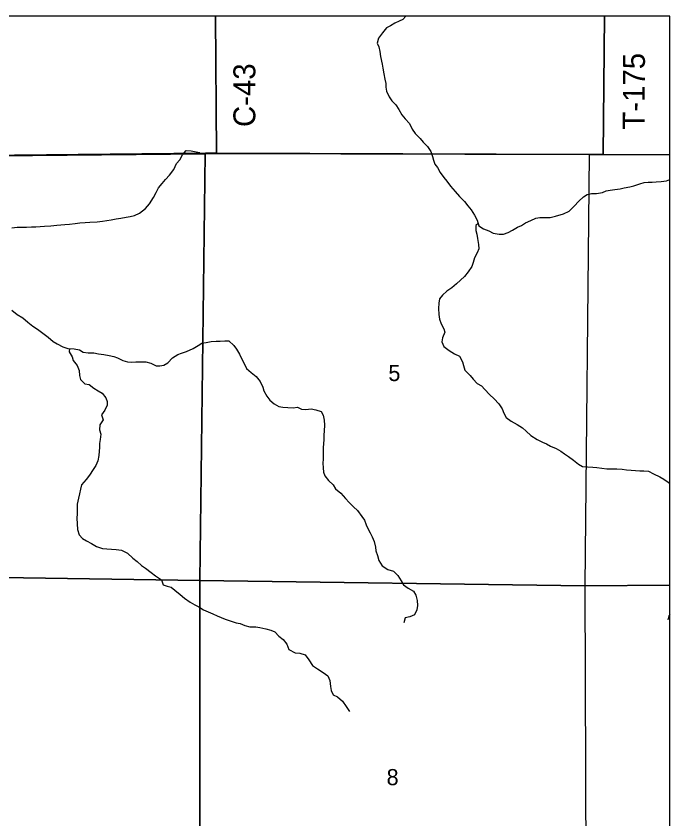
# Model space of a CAD drawing. Extents: x 1772825 to 1773716, y 1138558 to 1139032.
# Drawn here: x 1772831.311 to 1772832.158, y 1138563.32 to 1138564.359 of the extents above; entities that cross this region are included whole.
import ezdxf

# ---------------------------------------------------------------- set-up
doc = ezdxf.new("R2010")
doc.units = 0
for name, color, linetype in [('GM_X_County_Road_Text', 7, 'Continuous'), ('GM_X_Minor_River', 7, 'Continuous'), ('GM_X_Section', 7, 'Continuous'), ('GM_X_Section_Text', 7, 'Continuous'), ('GM_X_Township', 7, 'Continuous'), ('GM_X_Township_Road_Text', 7, 'Continuous')]:
    doc.layers.add(name, color=color, linetype=linetype)

msp = doc.modelspace()

# ---------------------------------------------------------------- linework, layer by layer
at = {"layer": 'GM_X_Minor_River'}
for points in [[(1772831.8157, 1138564.3594), (1772831.8122, 1138564.3551), (1772831.8071, 1138564.353), (1772831.8018, 1138564.3504), (1772831.7959, 1138564.347), (1772831.7908, 1138564.344), (1772831.7856, 1138564.3378), (1772831.7807, 1138564.331), (1772831.7789, 1138564.3242), (1772831.7808, 1138564.3194), (1772831.7821, 1138564.3137), (1772831.7832, 1138564.3071), (1772831.7854, 1138564.2972), (1772831.7863, 1138564.2919), (1772831.7874, 1138564.2847), (1772831.7889, 1138564.2779), (1772831.7898, 1138564.2722), (1772831.7898, 1138564.2672), (1772831.7907, 1138564.2623), (1772831.7942, 1138564.2549), (1772831.7976, 1138564.2499), (1772831.8031, 1138564.2444), (1772831.8068, 1138564.2385), (1772831.8107, 1138564.2315), (1772831.8149, 1138564.2263), (1772831.8205, 1138564.2202), (1772831.8242, 1138564.2132), (1772831.8278, 1138564.2075)], [(1772831.8278, 1138564.2075), (1772831.8344, 1138564.201), (1772831.8385, 1138564.1961), (1772831.8438, 1138564.1907), (1772831.8481, 1138564.1841), (1772831.8505, 1138564.1778), (1772831.8516, 1138564.1727), (1772831.8533, 1138564.1679), (1772831.8569, 1138564.1632), (1772831.8602, 1138564.1569), (1772831.8651, 1138564.1504), (1772831.8692, 1138564.1455), (1772831.8736, 1138564.1392), (1772831.8798, 1138564.1323), (1772831.8852, 1138564.126), (1772831.892, 1138564.1193), (1772831.8961, 1138564.1136), (1772831.9004, 1138564.1087), (1772831.9047, 1138564.1018), (1772831.9083, 1138564.0954), (1772831.9103, 1138564.088), (1772831.9166, 1138564.0838), (1772831.9232, 1138564.0813), (1772831.9292, 1138564.0784), (1772831.9366, 1138564.077), (1772831.9422, 1138564.0772), (1772831.9483, 1138564.0794), (1772831.9542, 1138564.0822), (1772831.9606, 1138564.0862), (1772831.9656, 1138564.0882), (1772831.9709, 1138564.0916), (1772831.9779, 1138564.0948), (1772831.9842, 1138564.0978), (1772831.9893, 1138564.0985), (1772831.9959, 1138564.0987), (1772832.0027, 1138564.0988), (1772832.0099, 1138564.1003), (1772832.0201, 1138564.1033), (1772832.0272, 1138564.1068), (1772832.0338, 1138564.1134), (1772832.0399, 1138564.1197), (1772832.0458, 1138564.1253), (1772832.0507, 1138564.1285), (1772832.0564, 1138564.1296), (1772832.0627, 1138564.1298), (1772832.0704, 1138564.1311), (1772832.0754, 1138564.1331), (1772832.0807, 1138564.1342), (1772832.0867, 1138564.1348), (1772832.0935, 1138564.1359), (1772832.0988, 1138564.137), (1772832.1058, 1138564.1383), (1772832.111, 1138564.1396), (1772832.1187, 1138564.1424), (1772832.1244, 1138564.1438), (1772832.1295, 1138564.1444), (1772832.1348, 1138564.1445), (1772832.1399, 1138564.1447), (1772832.1466, 1138564.1454), (1772832.1536, 1138564.1461), (1772832.1579, 1138564.1477)], [(1772831.3057, 1138564.0851), (1772831.3127, 1138564.086), (1772831.3177, 1138564.0861), (1772831.3247, 1138564.0863), (1772831.3311, 1138564.0865), (1772831.3366, 1138564.0866), (1772831.3425, 1138564.087), (1772831.3479, 1138564.0875), (1772831.3563, 1138564.088), (1772831.364, 1138564.0887), (1772831.3691, 1138564.0893), (1772831.3742, 1138564.0896), (1772831.3803, 1138564.09), (1772831.3879, 1138564.0911), (1772831.3937, 1138564.0918), (1772831.4006, 1138564.0923), (1772831.4068, 1138564.0925), (1772831.4161, 1138564.0932), (1772831.4231, 1138564.0939), (1772831.4289, 1138564.0946), (1772831.4343, 1138564.0957), (1772831.4409, 1138564.097), (1772831.4469, 1138564.0979), (1772831.4536, 1138564.099), (1772831.4589, 1138564.0998), (1772831.4647, 1138564.1011), (1772831.4712, 1138564.1041), (1772831.4786, 1138564.1105), (1772831.4839, 1138564.1163), (1772831.4891, 1138564.1246), (1772831.4927, 1138564.1309), (1772831.4958, 1138564.1371), (1772831.5005, 1138564.1428), (1772831.5045, 1138564.1477), (1772831.5097, 1138564.1535), (1772831.5154, 1138564.1607), (1772831.519, 1138564.1686), (1772831.5234, 1138564.1735), (1772831.5269, 1138564.18), (1772831.5313, 1138564.1854), (1772831.5379, 1138564.1848), (1772831.5443, 1138564.1837), (1772831.5492, 1138564.1829)], [(1772831.9095, 1138564.0911), (1772831.9066, 1138564.0884), (1772831.9065, 1138564.0817), (1772831.908, 1138564.077), (1772831.9089, 1138564.0715), (1772831.9102, 1138564.0639), (1772831.9103, 1138564.0582), (1772831.9084, 1138564.0531), (1772831.905, 1138564.0465), (1772831.9032, 1138564.0402), (1772831.9015, 1138564.0353), (1772831.8967, 1138564.0285), (1772831.8918, 1138564.0223), (1772831.8867, 1138564.0177), (1772831.8813, 1138564.0128), (1772831.8754, 1138564.0074), (1772831.869, 1138564.0032), (1772831.8633, 1138563.9983), (1772831.8595, 1138563.9934), (1772831.8585, 1138563.9876), (1772831.8581, 1138563.9809), (1772831.8586, 1138563.973), (1772831.8593, 1138563.9671), (1772831.8615, 1138563.9608), (1772831.8651, 1138563.9547), (1772831.8662, 1138563.95), (1772831.8635, 1138563.943), (1772831.8624, 1138563.9379), (1772831.8653, 1138563.9318), (1772831.8721, 1138563.9266), (1772831.8789, 1138563.9222), (1772831.8855, 1138563.919), (1772831.8894, 1138563.9119), (1772831.8907, 1138563.907), (1772831.8924, 1138563.9011), (1772831.899, 1138563.894), (1772831.9033, 1138563.8893), (1772831.9084, 1138563.8838), (1772831.9137, 1138563.8807), (1772831.9182, 1138563.8759), (1772831.9244, 1138563.8693), (1772831.9304, 1138563.8641), (1772831.9362, 1138563.8574), (1772831.9405, 1138563.851), (1772831.943, 1138563.8453), (1772831.946, 1138563.8397), (1772831.9524, 1138563.8348), (1772831.9601, 1138563.8308), (1772831.9669, 1138563.8264), (1772831.9718, 1138563.822), (1772831.9776, 1138563.8164), (1772831.9859, 1138563.8113), (1772831.9929, 1138563.808), (1772831.998, 1138563.8057), (1772832.0033, 1138563.8028), (1772832.0104, 1138563.7996), (1772832.0165, 1138563.7961), (1772832.0215, 1138563.7929), (1772832.0264, 1138563.7892), (1772832.033, 1138563.7846), (1772832.0396, 1138563.7793), (1772832.0447, 1138563.7764), (1772832.051, 1138563.7758), (1772832.0579, 1138563.7754), (1772832.0634, 1138563.775), (1772832.0699, 1138563.774), (1772832.0761, 1138563.7732), (1772832.0835, 1138563.7734), (1772832.0891, 1138563.7731), (1772832.0961, 1138563.7729), (1772832.1018, 1138563.7721), (1772832.1079, 1138563.7715), (1772832.1132, 1138563.7711), (1772832.119, 1138563.7709), (1772832.1239, 1138563.7707), (1772832.1302, 1138563.7701), (1772832.1364, 1138563.767), (1772832.1447, 1138563.7628), (1772832.15, 1138563.7597), (1772832.1554, 1138563.7561), (1772832.1579, 1138563.7542)], [(1772831.3057, 1138563.9785), (1772831.3125, 1138563.973), (1772831.3198, 1138563.9686), (1772831.3262, 1138563.963), (1772831.3328, 1138563.9579), (1772831.339, 1138563.9541), (1772831.346, 1138563.9487), (1772831.3526, 1138563.9437), (1772831.3594, 1138563.938), (1772831.3645, 1138563.935), (1772831.3718, 1138563.9313), (1772831.3784, 1138563.929), (1772831.3865, 1138563.9288), (1772831.3932, 1138563.9272), (1772831.3981, 1138563.9245), (1772831.4045, 1138563.9234), (1772831.4119, 1138563.9233), (1772831.4179, 1138563.9221), (1772831.4247, 1138563.9212), (1772831.4319, 1138563.9202), (1772831.4376, 1138563.9188), (1772831.4425, 1138563.9169), (1772831.4495, 1138563.9136), (1772831.4553, 1138563.9119), (1772831.4606, 1138563.9113), (1772831.4663, 1138563.9116), (1772831.4791, 1138563.9116), (1772831.4858, 1138563.91), (1772831.4924, 1138563.9066), (1772831.4975, 1138563.9065), (1772831.5026, 1138563.9074), (1772831.5079, 1138563.9103), (1772831.5136, 1138563.9171), (1772831.5208, 1138563.9214), (1772831.5256, 1138563.9232), (1772831.532, 1138563.9253), (1772831.5405, 1138563.9289), (1772831.547, 1138563.933), (1772831.5519, 1138563.936), (1772831.5574, 1138563.9369), (1772831.564, 1138563.938), (1772831.5705, 1138563.9385), (1772831.5754, 1138563.9387), (1772831.5813, 1138563.9392), (1772831.5869, 1138563.939), (1772831.5931, 1138563.9331), (1772831.5967, 1138563.9282), (1772831.6006, 1138563.9217), (1772831.6033, 1138563.9162), (1772831.6072, 1138563.908), (1772831.6094, 1138563.9032), (1772831.6156, 1138563.8979), (1772831.6219, 1138563.8929), (1772831.6273, 1138563.8865), (1772831.6305, 1138563.8791), (1772831.632, 1138563.8743), (1772831.6361, 1138563.8673), (1772831.6398, 1138563.8623), (1772831.6455, 1138563.8574), (1772831.6515, 1138563.8539), (1772831.6564, 1138563.8533), (1772831.6632, 1138563.8527), (1772831.67, 1138563.8523), (1772831.6757, 1138563.853), (1772831.6806, 1138563.8505), (1772831.6865, 1138563.8499), (1772831.6933, 1138563.8508), (1772831.6995, 1138563.8495), (1772831.7061, 1138563.8475), (1772831.709, 1138563.8428), (1772831.7102, 1138563.8361), (1772831.7104, 1138563.8297), (1772831.71, 1138563.8225), (1772831.7096, 1138563.8168), (1772831.7099, 1138563.8113), (1772831.7093, 1138563.8056), (1772831.7089, 1138563.8009), (1772831.7088, 1138563.7908), (1772831.709, 1138563.7857), (1772831.7086, 1138563.7806), (1772831.7089, 1138563.7745), (1772831.7093, 1138563.769), (1772831.7111, 1138563.7641), (1772831.7158, 1138563.758)], [(1772831.3802, 1138563.9289), (1772831.3801, 1138563.9248), (1772831.3837, 1138563.9184), (1772831.3851, 1138563.9134), (1772831.3902, 1138563.9071), (1772831.3928, 1138563.9007), (1772831.3935, 1138563.8942), (1772831.3946, 1138563.8889), (1772831.4003, 1138563.8834), (1772831.4058, 1138563.8824), (1772831.4118, 1138563.8776), (1772831.4176, 1138563.8742), (1772831.4225, 1138563.8711), (1772831.4274, 1138563.8652), (1772831.4293, 1138563.8605), (1772831.4291, 1138563.8557), (1772831.4262, 1138563.8493), (1772831.422, 1138563.843), (1772831.4238, 1138563.8366), (1772831.4198, 1138563.8304), (1772831.4194, 1138563.8237), (1772831.4211, 1138563.8182), (1772831.4201, 1138563.8112), (1772831.4191, 1138563.8061), (1772831.4191, 1138563.801), (1772831.4189, 1138563.796), (1772831.4183, 1138563.7904), (1772831.4169, 1138563.7837), (1772831.4146, 1138563.7777), (1772831.411, 1138563.7722), (1772831.4064, 1138563.7652), (1772831.4018, 1138563.7593), (1772831.3957, 1138563.7527), (1772831.3944, 1138563.7469), (1772831.3934, 1138563.7408), (1772831.3919, 1138563.7353), (1772831.3905, 1138563.7277), (1772831.3904, 1138563.7149), (1772831.39, 1138563.7092), (1772831.3903, 1138563.702), (1772831.3909, 1138563.6946), (1772831.3927, 1138563.6879), (1772831.397, 1138563.6831), (1772831.4023, 1138563.6799), (1772831.4089, 1138563.6768), (1772831.4155, 1138563.6726), (1772831.4233, 1138563.6703), (1772831.4287, 1138563.6699), (1772831.4348, 1138563.6693), (1772831.441, 1138563.6689), (1772831.4478, 1138563.6681), (1772831.4554, 1138563.6641), (1772831.4625, 1138563.6578), (1772831.4678, 1138563.6534), (1772831.4736, 1138563.648), (1772831.4789, 1138563.6448), (1772831.4859, 1138563.6389), (1772831.4919, 1138563.6346), (1772831.4996, 1138563.6295), (1772831.5015, 1138563.623), (1772831.507, 1138563.6215), (1772831.5119, 1138563.6199), (1772831.5168, 1138563.6161), (1772831.5237, 1138563.6106), (1772831.5294, 1138563.6058), (1772831.5365, 1138563.6006), (1772831.5426, 1138563.597), (1772831.5477, 1138563.5947), (1772831.5539, 1138563.5909), (1772831.5599, 1138563.5882), (1772831.5661, 1138563.5855), (1772831.5714, 1138563.5828), (1772831.5767, 1138563.5809), (1772831.582, 1138563.5788), (1772831.5884, 1138563.5765), (1772831.5962, 1138563.5741), (1772831.6014, 1138563.573), (1772831.6073, 1138563.5705), (1772831.6139, 1138563.5689), (1772831.6215, 1138563.5687), (1772831.627, 1138563.5679), (1772831.6345, 1138563.566), (1772831.6411, 1138563.5642), (1772831.6462, 1138563.5621), (1772831.6513, 1138563.5566), (1772831.6571, 1138563.5522), (1772831.6616, 1138563.5465), (1772831.6646, 1138563.5393), (1772831.6725, 1138563.535), (1772831.6786, 1138563.5346), (1772831.6854, 1138563.5325), (1772831.6903, 1138563.526), (1772831.6951, 1138563.5188), (1772831.7017, 1138563.5142), (1772831.7087, 1138563.5096), (1772831.7147, 1138563.5052), (1772831.7174, 1138563.4993), (1772831.7183, 1138563.4915), (1772831.7192, 1138563.4862), (1772831.7216, 1138563.4807), (1772831.7274, 1138563.478)], [(1772831.7158, 1138563.758), (1772831.7219, 1138563.7526), (1772831.725, 1138563.7475), (1772831.7316, 1138563.7418), (1772831.7378, 1138563.7349), (1772831.7425, 1138563.7296), (1772831.7482, 1138563.7239), (1772831.7531, 1138563.7195), (1772831.7591, 1138563.7117), (1772831.7623, 1138563.7069), (1772831.7645, 1138563.7008), (1772831.7669, 1138563.6961), (1772831.7697, 1138563.6904), (1772831.7722, 1138563.6852), (1772831.7748, 1138563.679), (1772831.7764, 1138563.6719), (1772831.7772, 1138563.6672), (1772831.7792, 1138563.6609), (1772831.7811, 1138563.6548), (1772831.7852, 1138563.6478), (1772831.7927, 1138563.6428), (1772831.7999, 1138563.6409), (1772831.8057, 1138563.635), (1772831.8097, 1138563.6283), (1772831.813, 1138563.623), (1772831.8191, 1138563.6188), (1772831.8257, 1138563.6148), (1772831.829, 1138563.6098), (1772831.8305, 1138563.6028), (1772831.8312, 1138563.5965), (1772831.8303, 1138563.5909), (1772831.8272, 1138563.5842), (1772831.8211, 1138563.5816), (1772831.8152, 1138563.5803), (1772831.8135, 1138563.5739)], [(1772832.1579, 1138563.5846), (1772832.1565, 1138563.583), (1772832.155, 1138563.5778)], [(1772831.7274, 1138563.478), (1772831.734, 1138563.4723), (1772831.7387, 1138563.4658), (1772831.743, 1138563.4592)]]:
    msp.add_lwpolyline(points, dxfattribs=at)
at = {"layer": 'GM_X_Section'}
for p, q in [((1772831.5696, 1138564.3594), (1772831.0224, 1138564.3594)), ((1772832.073, 1138564.3594), (1772831.5696, 1138564.3594)), ((1772832.1579, 1138563.6228), (1772832.1579, 1138564.1799)), ((1772832.1579, 1138563.1369), (1772832.1579, 1138563.6228))]:
    msp.add_line(p, q, dxfattribs=at)
for points in [[(1772831.0224, 1138564.3594), (1772831.0192, 1138564.1759), (1772831.556, 1138564.1812), (1772831.5706, 1138564.1813), (1772831.5696, 1138564.3594)], [(1772831.5696, 1138564.3594), (1772831.5706, 1138564.1813), (1772832.0531, 1138564.1804), (1772832.0714, 1138564.1803), (1772832.073, 1138564.3594)], [(1772832.073, 1138564.3594), (1772832.0714, 1138564.1803), (1772832.1579, 1138564.1799)], [(1772832.1579, 1138564.1799), (1772832.1579, 1138564.3594), (1772832.073, 1138564.3594)], [(1772832.1579, 1138564.1799), (1772832.0714, 1138564.1803), (1772832.0531, 1138564.1804), (1772832.0479, 1138563.6217), (1772832.1579, 1138563.6228)], [(1772832.1579, 1138563.6228), (1772832.0479, 1138563.6217), (1772832.0494, 1138563.1364), (1772832.1579, 1138563.1369)]]:
    msp.add_lwpolyline(points, dxfattribs=at)
for points in [[(1772831.0192, 1138564.1759), (1772831.556, 1138564.1812), (1772831.5492, 1138563.6286), (1772831.0064, 1138563.637), (1772831.0062, 1138563.6401)], [(1772831.556, 1138564.1812), (1772831.5706, 1138564.1813), (1772832.0531, 1138564.1804), (1772832.0479, 1138563.6217), (1772831.5492, 1138563.6286)], [(1772831.0064, 1138563.637), (1772831.5492, 1138563.6286), (1772831.5492, 1138563.1342), (1772831.0143, 1138563.1351), (1772831.0148, 1138563.1381)], [(1772831.5492, 1138563.6286), (1772832.0479, 1138563.6217), (1772832.0494, 1138563.1364), (1772831.5492, 1138563.1342)]]:
    msp.add_lwpolyline(points, close=True, dxfattribs=at)
at = {"layer": 'GM_X_Township'}
msp.add_line((1772832.1579, 1138561.1331), (1772832.1579, 1138564.1796), dxfattribs=at)
for points in [[(1772831.0226, 1138564.3594), (1772831.0202, 1138564.1762), (1772831.5563, 1138564.1819), (1772831.5706, 1138564.1819), (1772832.0538, 1138564.1803), (1772832.0716, 1138564.1801), (1772832.1579, 1138564.1796)], [(1772832.1579, 1138564.1796), (1772832.1579, 1138564.3594), (1772831.0226, 1138564.3594)], [(1772832.1579, 1138564.1796), (1772832.0716, 1138564.1801), (1772832.0538, 1138564.1803), (1772831.5706, 1138564.1819), (1772831.5563, 1138564.1819), (1772831.0202, 1138564.1762), (1772831.0121, 1138563.891), (1772831.0052, 1138563.6394), (1772831.0051, 1138563.6356), (1772831.0123, 1138563.1356), (1772831.0184, 1138562.6335), (1772831.0189, 1138562.1254), (1772831.0162, 1138561.6278), (1772831.0118, 1138561.1299), (1772831.4841, 1138561.1316), (1772831.5117, 1138561.1318), (1772832.1579, 1138561.1331)]]:
    msp.add_lwpolyline(points, dxfattribs=at)

# ---------------------------------------------------------------- texts
at = {"layer": 'GM_X_County_Road_Text'}
msp.add_text('C-43', height=0.02841, rotation=90, dxfattribs=at).set_placement((1772831.621, 1138564.2158))
at = {"layer": 'GM_X_Section_Text'}
for s, p in [('5', (1772831.7933, 1138563.8869)), ('8', (1772831.791, 1138563.3637))]:
    msp.add_text(s, height=0.0209, rotation=0, dxfattribs=at).set_placement(p)
at = {"layer": 'GM_X_Township_Road_Text'}
msp.add_text('T-175', height=0.02841, rotation=89.7221, dxfattribs=at).set_placement((1772832.1251, 1138564.2124))

doc.saveas('drawing.dxf')
